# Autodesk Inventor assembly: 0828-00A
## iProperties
Shininess: 64.0
Length Units: 11269
Angle Units: 11279
Time Units: 11290
Mass Units: 11283
Length Display Precision: 3
Angle Display Precision: 2
Compacted: True
Created: 2003-08
Part Number: 0828-00A
Document SubType Name: Assembly
Designer: 40664
Manufacturer: Standard
Standards Organization: Custom
Density: 0.0
Volumn: 0.0
Area: 0.0
PropertySet Name: Model Information
Control State: 0
Master: False
Checked Out: False
Author: 40664
